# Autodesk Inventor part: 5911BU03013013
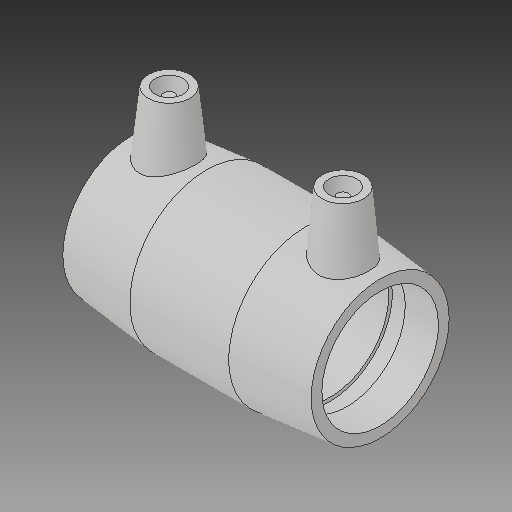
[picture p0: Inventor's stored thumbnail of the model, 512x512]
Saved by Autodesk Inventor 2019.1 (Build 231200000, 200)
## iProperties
Created: 2017-06
Part Number: 5911BU03013013
Material: Generic
Description: PLASSON ASTM REDUCING COUPLER 1 1/4''IPS-1 1/4''CTS
Document SubType Name: Modeling
Designer: KIM
Mass: 54.8237 g
Surface Area: 155.252 cm^2
Volume: 54.8237 cm^3
Density: 1 g/cm^3
Appearance: Default
Author: KIM
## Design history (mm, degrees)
derived "5911.ipt"
feature "Solid1::5911.ipt"
tag "TaggingFeature1"
body "Solid1"
other parameters: "d0" = 89.662, "d2" = 55.372, "d3" = 44.958, "d4" = 26.9748, "d5" = 49.8348, "d7" = 34.8, "d8" = 168 deg, "d10" = 17.9832, "d11" = 5.9944, "d14" = 17.6296, "d22" = 108.92847, "d29" = 46.99, "d30" = 15, "d31" = 31.3817, "d34" = 6 deg, "d41" = 4, "d42" = 14, "d43" = 0, "d48" = 55.372, "d49" = 42.1, "d50" = 55.372, "d52" = 31.32, "d53" = 17.9832, "d54" = 5.9944, "d55" = 168 deg, "d56" = 26.9748, "d57" = 44.958, "d58" = 49.8348, "d59" = 2.2479, "d60" = 135 deg, "d61" = 46.99, "d62" = 15, "d64" = 4, "d66" = 5 deg, "d67" = 14, "d68" = 0, "d69" = 31.3817, "d95" = 3, "d96" = 0, "d97" = 3, "d98" = 0, "d_1" = 34.8, "L_" = 89.662, "L_2" = 44.958, "D_1" = 55.372, "A_1" = 46.99, "d_2" = 12, "L_1" = 44.958, "d_" = 42.1, "A_" = 46.99, "D_" = 55.372
